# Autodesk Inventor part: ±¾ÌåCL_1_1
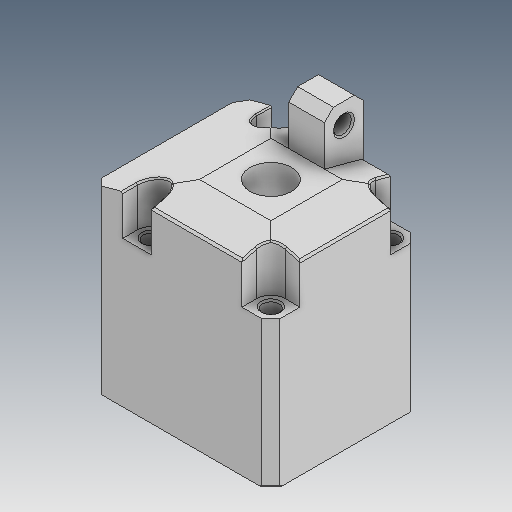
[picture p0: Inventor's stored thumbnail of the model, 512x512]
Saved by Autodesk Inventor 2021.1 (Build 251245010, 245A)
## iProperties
Created: 2019-04
Part Number: ±¾ÌåCL_1_1
Material: Ogólny
Document SubType Name: Modeling
Designer: user
Density: 1 g/cm^3
Appearance: Domyślna
Author: user
Revision Number: ÈÎºÎ
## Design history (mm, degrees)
feature "Í¹Ì¨-À­Éì1"
node "Bryła1"
